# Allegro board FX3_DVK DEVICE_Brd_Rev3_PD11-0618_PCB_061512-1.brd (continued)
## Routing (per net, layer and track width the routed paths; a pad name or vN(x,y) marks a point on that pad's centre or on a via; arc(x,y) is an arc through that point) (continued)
VIO2: length 1.2
  TOP w0.254: U1.F1 64.64,66.55 64.64,67.64 v2(64.71,67.71)
  vias: v2(64.73,68.26)
VIO3: length 1.6
  TOP w0.254: U1.E3 65.23,65.16 65.23,65.16 v2(65.04,65.35)
  BOTTOM w0.381: C111.1 65.27,65.57 v2(65.04,65.35) 65.29,65.1 C110.1
VIO4: length 11
  TOP w0.254: v2(68.24,66.95) 68.03,66.73 68.03,66.73 U1.B1
  TOP w0.381: v1(61.73,92.78) 61.63,92.88 U7.1
  TOP w0.508: R248.1 58.6,109.53 v3(58.17,109.09) ; R250.1 v1(61.54,97.21)
  TOP w0.635: U26.8 v3(58.17,109.09)
  BOTTOM w0.483: C36.1 v1(61.73,92.78)
  BOTTOM w0.508: R249.1 v3(57.21,97.03) ; R248.1 58.6,109.53 v3(58.17,109.09) ; R252.1 v1(62.93,110.93) ; R246.1 v3(58.6,96.96) ; R36.2 v3(65.64,90.11)
VIO5: length 8.7
  TOP w0.254: U1.C11 67.04,58.55 v2(67.04,57.98)
  TOP w0.508: R51.2 v3(22.52,28.65) ; R53.2 v3(22.52,17.09) ; R55.2 v3(22.52,12.01) ; R52.2 v3(22.52,18.87) ; R54.2 v3(22.52,14.55)
  BOTTOM w0.508: R263.1 v3(34.16,113.47)
  BOTTOM w0.635: C197.1 v3(29.08,117.86) ; R262.1 v3(31.62,113.54) ; R176.2 v3(46.68,101.22) ; C212.1 v3(27.94,117.86) ; R186.2 v3(52.38,101.22) ; R110.1 v3(36.83,113.47)
XTALIN: length 19.6
  TOP w0.203: v2(67.44,62.15) 67.2,62.4 U1.C6
  TOP w0.483: Y3.1 77.47,74.08 ; C216.2 v1(77.44,71.93)
  TOP w0.508: 77.47,74.08 C216.2
  SIG2#6 w0.127: v1(77.44,71.93) arc(77.34,71.45) 77.07,71.04 68.71,62.69 arc(68.57,62.59) 68.39,62.55 67.85,62.55 arc(67.56,62.43) v2(67.44,62.15)
XTALOUT: length 20.7
  TOP w0.203: U1.C7 67.24,61.55 v2(67.44,61.35)
  TOP w0.483: v1(80.1,69.51) 80.14,69.48 C217.1 81.64,69.49 81.64,71.94
  TOP w0.508: 81.64,71.94 Y3.3
  SIG2#6 w0.127: v1(80.1,69.51) 77.05,69.51 arc(76.47,69.4) 75.99,69.07 68.89,61.98 arc(68.64,61.81) 68.34,61.75 67.85,61.75 arc(67.56,61.63) v2(67.44,61.35)
N13394127: length 41.3
  TOP w0.254: U1.E10 v2(65.84,58.95)
  SIG2#6 w1.27: 66.65,56.66 66.65,56.14 66.73,56.14 68.29,54.58 68.29,52.03 55.04,38.78 51.45,38.78 43.14,30.48 J74.1
  BOTTOM w0.381: C53.1 65.67,59.12 v2(65.84,58.95)
N13841009: length 2.1
  TOP w0.432: v1(65.53,89.03) 65.58,88.98 U7.8
  BOTTOM w0.483: v1(65.53,89.03) 65.72,89.21 R36.1
N13880067: length 10.3
  TOP w0.432: U6.16 73.86,93.65 75.65,95.44 75.65,96.86 76.96,98.17 R29.2
N13882405: length 10.1
  TOP w0.432: R25.2 80.26,97.16 79.88,97.54 77.83,97.54 76.53,96.23 76.53,95.32 74.21,93 U6.17
N13882880: length 1.8
  TOP w0.432: U6.9 80.71,96.26 R27.2
N13883880: length 1.9
  TOP w0.432: R33.2 80.31,95.12 79.83,95.61 U6.8
N13897864: length 2.1
  TOP w0.432: R32.1 71.83,95.63 72.45,96.26 U6.12
N13897866: length 2.1
  TOP w0.432: U6.15 72.68,94.31 71.97,93.6 R28.1
N13897868: length 2
  TOP w0.432: U6.10 78.11,96.91 v1(77.98,96.78)
  BOTTOM w0.483: R26.1 77.44,96.77 77.45,96.78 v1(77.98,96.78)
N13897870: length 2.2
  TOP w0.432: U6.13 72.7,95.61 71.71,94.61 R24.1
N13929197: length 1.9
  TOP w0.432: U6.2 79.98,91.7 80.32,91.37 C33.1
N13930227: length 2.1
  TOP w0.432: C33.2 80.48,92.27 79.77,92.99 79.14,92.99 U6.4
N13931322: length 1.9
  TOP w0.432: C35.1 80.44,93.28 80.06,93.65 U6.5
N13931334: length 1.8
  TOP w0.432: U6.6 80.31,94.31 80.44,94.18 80.9,94.18 C35.2
N13944533: length 2.2
  TOP w0.432: U6.3 78.33,92.35 78.23,92.46 78.18,92.46 v3(78.13,92.51)
  BOTTOM w0.483: v3(78.13,92.51) 78.18,92.46 78.23,92.46 78.43,92.26 C32.1
N13945074: length 2
  TOP w0.432: U6.7 78.26,94.96 v3(78.13,94.83)
  BOTTOM w0.483: v3(78.13,94.83) 78.16,94.8 C34.1
N16663499: length 1.8
  TOP w0.254: X2.7 v1(75.31,56.88)
  BOTTOM w0.483: v1(75.31,56.88) 75.29,56.9 R43.2
N17020961:
  vias: v3(91.25,29.35) v3(91.25,28.49) v3(92.29,29.66) v3(93.18,29.62)
N17052408: length 3.2
  TOP w0.305: C43.1 71.43,63.2 68.99,63.2 arc(68.8,63.24) U1.A5
N17056303: length 3.2
  TOP w0.305: C46.1 71.43,62.7 68.99,62.7 arc(68.8,62.66) U1.A6
N17073855: length 4.1
  TOP w0.127: v4(95.5,53.1) 95.63,53.1 J48.11 ; v4(95.5,63.64) 95.63,63.64 J48.15 ; v4(95.5,56.02) 95.63,56.02 J48.12 ; J48.16 95.63,66.18 v4(95.5,66.18) ; J48.14 95.63,61.1 v4(95.5,61.1) ; J48.13 95.63,58.31 v4(95.5,58.31)
  vias: v4(92.46,67.07) v4(92.46,52.34) v4(93.47,67.07) v4(93.47,52.34) v4(94.49,66.18) v4(94.49,63.64) v4(94.49,61.1) v4(94.49,58.31) v4(94.49,56.02) v4(94.49,53.1) v4(94.8,48.76) v4(95.4,47.45) v4(95.46,46.45)
N17441604: length 1.8
  TOP w0.254: v2(68.24,65.35) 67.84,64.95 U1.B3
  BOTTOM w0.381: v2(68.24,65.35) 68.98,66.08 69.15,66.08 R47.1
N17441606: length 5
  TOP w0.254: U1.C8 v2(67.44,60.55)
  BOTTOM w0.305: v2(67.44,60.55) 68.24,60.55 68.54,60.25 69.42,60.25 69.44,60.23 69.45,60.23 69.46,60.22 69.6,60.07 69.6,60.07 69.61,60.06 69.61,60.05 69.81,59.86 70.79,59.86 71.13,59.52 R48.1
N17676874: length 1.6
  TOP w0.254: X2.1 v1(79.35,54.38)
  BOTTOM w0.508: R40.2 80.09,54.38 v1(79.35,54.38)
N20153874:
  vias: v3(88.98,55) v3(89.66,55) v3(90.72,54.44) v3(90.69,53.74) v3(92.1,55.2) v3(92.8,55.2)
N20184217: length 15.8
  TOP w0.127: U1.F10 64.45,59.16 64.45,59.16 v2(64.24,58.95)
  SIG2#6 w0.127: v2(64.24,58.95) 63.84,58.55 63.84,57.89 63.47,57.51 63.2,57.51 60.64,54.95 53.84,54.95 v1(53.56,55.23)
  BOTTOM w0.483: R5.1 52.14,56.11 53.02,55.23 v1(53.56,55.23)
N20186132: length 16.7
  TOP w0.127: U1.F9 64.43,59.94 64.43,59.94 v2(64.24,59.75)
  SIG2#6 w0.127: v2(64.24,59.75) 64.24,59.75 63.85,59.35 63.29,59.35 63.05,59.11 63.05,57.9 60.58,55.43 53.99,55.43 53.74,55.68 53.29,56.13 v1(53.08,56.13)
  BOTTOM w0.483: R205.1 52.29,57.78 52.62,57.46 52.62,57.46 52.83,57.25 52.83,56.38 v1(53.08,56.13)
N20187007: length 12.2
  TOP w0.127: U1.F7 64.47,61.58 64.47,61.58 v2(64.24,61.35)
  TOP w0.483: v1(56.32,60.26) 55.76,60.26 R206.1
  SIG1#3 w0.127: v1(56.32,60.26) 56.37,60.26 58.39,58.24 60.9,58.24 61.45,58.8 61.45,59.11 61.68,59.34 63.59,59.34 63.85,59.6 63.85,60.38 63.85,60.95 v2(64.24,61.35)
N20187884: length 10.4
  TOP w0.127: U1.G10 63.63,59.14 63.63,59.14 v2(63.44,58.95)
  SIG1#3 w0.127: v2(63.44,58.95) 63.06,58.56 63.06,57.9 61.83,56.67 v1(55.7,56.67)
  BOTTOM w0.483: R207.1 v1(55.7,56.67)
N20188787: length 15.5
  TOP w0.127: U1.G9 63.84,60.15 v2(63.44,59.75)
  TOP w0.483: R208.1 52.14,57.93 53.48,56.59 v1(53.72,56.59)
  SIG2#6 w0.127: v1(53.72,56.59) 54.77,56.59 55.16,56.19 60.44,56.19 62.01,57.76 62.24,57.99 62.24,58.13 62.24,58.14 62.24,59.11 62.48,59.35 62.81,59.35 63.2,59.75 v2(63.44,59.75)
N20188789: length 15.9
  TOP w0.127: v2(64.24,60.55) 64.46,60.76 64.46,60.76 U1.F8
  SIG2#6 w0.127: v2(64.24,60.55) 64.24,60.55 63.84,60.95 63.84,61.51 63.61,61.74 63.28,61.74 62.49,61.74 62.25,61.98 62.25,62.39 61.38,63.25 60.57,63.25 60.04,63.79 59.94,63.79 59.94,63.79 59.49,63.79 58.56,64.72 55.2,64.72 54.2,65.72 53.39,65.72 53.38,65.73 v1(53.24,65.73)
  BOTTOM w0.483: v1(53.24,65.73) 53.14,65.83 53.14,65.83 52.14,66.84 R209.1
N20188799: length 8.9
  TOP w0.127: v2(62.64,58.95) 62.85,59.16 62.85,59.16 U1.H10
  SIG1#3 w0.127: v2(62.64,58.95) 62.24,58.54 62.24,57.91 61.81,57.48 57.33,57.48 56.52,58.29 56.51,58.29 v1(56.45,58.35)
  BOTTOM w0.483: R210.1 56.29,58.42 56.32,58.39 56.37,58.39 56.41,58.35 v1(56.45,58.35)
N20188809: length 12.3
  TOP w0.127: U1.H9 62.84,59.95 62.84,59.95 v2(62.64,59.75)
  TOP w0.483: v1(52.81,61.62) 52.81,61.66 52.14,62.33 R211.1
  SIG2#6 w0.127: v1(52.81,61.62) 52.95,61.76 56.56,61.76 58.15,60.17 60.61,60.17 60.63,60.15 62.26,60.15 62.64,59.77 v2(62.64,59.75)
N20189728: length 8
  TOP w0.127: U1.J10 62.06,59.17 62.06,59.17 v2(61.84,58.95)
  SIG1#3 w0.127: v1(56.31,59.32) 56.32,59.32 56.39,59.25 56.55,59.25 57.93,57.87 58.31,57.87 58.31,57.86 61,57.86 61.84,58.71 v2(61.84,58.95)
  BOTTOM w0.483: R212.1 56.21,59.44 56.32,59.32 v1(56.31,59.32)
N20189730: length 13.3
  TOP w0.127: v2(61.84,59.75) 62.06,59.97 62.06,59.97 U1.J9
  SIG2#6 w0.127: v1(53.53,57.38) 53.53,57.37 53.78,57.11 59.97,57.11 61.45,58.6 61.45,59.35 v2(61.84,59.75)
  BOTTOM w0.483: R213.1 52.14,58.96 52.83,58.26 52.83,58.13 53.46,57.5 53.46,57.46 v1(53.53,57.38)
N20189740: length 8.6
  TOP w0.254: 61.21,58.29 61.44,58.52 U1.K11
  TOP w0.483: R214.1 56.38,62.1 57.02,61.46 57.02,59.96 58.98,58 60.92,58 61.21,58.29
N20189750: length 8.1
  TOP w0.203: U1.L10 60.64,59.35 60.63,59.34 59.87,59.34 59.82,59.29
  TOP w0.483: R215.1 56,63.58 56.69,63.58 56.73,63.54 56.76,63.54 57.76,62.53 57.76,60.39 58.87,59.29 59.82,59.29
N20190677: length 11.4
  TOP w0.127: U1.K10 61.23,59.14 61.23,59.14 v2(61.04,58.95)
  TOP w0.483: v1(52.95,59.11) 52.95,59.11 52.14,59.92 R216.1
  SIG2#6 w0.127: v1(52.95,59.11) 53.99,59.11 55.22,57.88 59.96,57.88 60.59,58.51 60.59,58.51 61.03,58.95 v2(61.04,58.95)
N20190679: length 11.1
  TOP w0.127: v2(61.04,59.75) 61.24,59.94 61.24,59.94 U1.K9
  SIG2#6 w0.127: v1(52.96,60.38) 53.44,60.85 53.71,60.85 53.71,60.85 54.08,60.85 54.08,60.85 56.1,60.85 56.18,60.77 56.57,60.77 57.12,60.23 57.12,60.22 57.99,59.35 60.65,59.35 61.04,59.75 v2(61.04,59.75)
  BOTTOM w0.483: v1(52.96,60.38) 52.86,60.49 52.85,60.49 52.14,61.19 R217.1
N20190689: length 8.1
  TOP w0.127: U1.J8 62.05,60.76 v2(61.84,60.55)
  SIG1#3 w0.127: v1(56.45,62.98) 56.98,62.98 59.79,60.17 60.62,60.17 60.64,60.14 61.24,60.14 61.65,60.55 v2(61.84,60.55)
  BOTTOM w0.483: v1(56.45,62.98) 56.44,62.97 56.05,62.97 56.03,62.99 R218.1
N20190699: length 9.8
  TOP w0.127: U1.G8 v2(63.44,60.55)
  SIG1#3 w0.127: v2(63.44,60.55) 63.04,60.15 61.69,60.15 61.45,59.91 61.45,59.59 61.22,59.35 58.22,59.35 v1(56.37,61.21)
  BOTTOM w0.483: v1(56.37,61.21) R219.1
N20191634: length 9.1
  TOP w0.127: U1.J6 62.03,62.34 62.03,62.34 v2(61.84,62.15)
  SIG1#3 w0.127: v2(61.84,62.15) 61.84,62.15 61.43,61.74 60.85,61.74 60.4,62.19 60.4,62.32 60.17,62.55 59.62,62.55 56.92,65.25 56.92,65.61 56.47,66.06 56.47,66.07 v1(56.44,66.09)
  BOTTOM w0.483: R220.1 v1(56.44,66.09)
N20191636: length 7.7
  TOP w0.127: U1.K8 61.29,60.79 61.29,60.79 v2(61.04,60.55)
  SIG1#3 w0.127: v1(56.35,64.28) 56.35,64.15 59.96,60.55 v2(61.04,60.55)
  BOTTOM w0.381: R221.1 55.81,64.77 56.3,64.28 v1(56.35,64.28)
N20191646: length 10.6
  TOP w0.127: v2(61.04,61.35) 61.25,61.56 U1.K7
  TOP w0.483: v1(52.87,63.47) 52.83,63.51 52.82,63.51 52.2,64.14 R222.1
  SIG2#6 w0.127: v2(61.04,61.35) 60.65,61.35 60.26,61.75 57.65,61.75 56.88,62.52 56.07,62.52 55.55,63.04 53.3,63.04 v1(52.87,63.47)
N20191656: length 12
  TOP w0.127: v2(61.84,61.35) 62.05,61.55 62.05,61.56 U1.J7
  SIG2#6 w0.127: v1(53.42,63.8) 53.55,63.93 54.44,63.93 54.91,63.45 58.6,63.45 59.45,62.6 60.13,62.6 60.65,62.08 60.65,61.96 60.86,61.75 61.41,61.75 61.81,61.35 v2(61.84,61.35)
  BOTTOM w0.483: R223.1 52.2,65.02 53.42,63.81 v1(53.42,63.8)
N20192599: length 13.1
  TOP w0.127: U1.H7 62.87,61.57 v2(62.64,61.35)
  TOP w0.483: R224.1 v1(56.49,69.22)
  SIG1#3 w0.127: v1(56.49,69.22) 57.16,68.54 57.16,67.31 60.33,64.14 61.21,64.14 62.01,63.34 62.81,63.34 63.04,63.1 U1.H7 v2(62.64,61.35)
N20192601: length 10.5
  TOP w0.127: U1.G7 63.65,61.56 63.65,61.55 v2(63.44,61.35)
  TOP w0.483: v1(56.46,65.17) 56.18,65.17 55.7,65.66 R225.1
  SIG1#3 w0.127: v1(56.46,65.17) 56.46,65.15 56.81,64.8 59.85,61.76 60.18,61.76 60.65,61.3 60.65,61.19 60.88,60.95 62.48,60.95 63.05,60.95 63.44,61.35 v2(63.44,61.35)
N20192611: length 15.2
  TOP w0.127: v2(63.44,62.95) 63.65,62.74 U1.G6
  TOP w0.483: R226.1 52.3,69.6 v1(52.79,69.1)
  SIG2#6 w0.127: v2(63.44,62.95) 63.44,62.95 63.04,63.35 63.04,63.94 62.83,64.15 62.49,64.15 62.24,64.4 62.24,64.71 62,64.95 60.17,64.95 60.17,64.95 60.08,64.95 59.85,65.19 59.83,65.19 56.91,68.1 55.17,68.1 54.62,68.65 53.25,68.65 52.8,69.1 v1(52.79,69.1)
N20192621: length 11.2
  TOP w0.127: U1.K6 61.04,62.15 v2(61.04,62.15)
  TOP w0.483: R227.1 52.14,65.94 52.68,65.4 52.68,65.4 53.31,64.77 v1(53.33,64.77)
  SIG2#6 w0.127: v1(53.33,64.77) 53.39,64.83 54.07,64.83 55.07,63.84 58.85,63.84 59.71,62.98 60.21,62.98 v2(61.04,62.15)
N20193572: length 12.3
  TOP w0.127: U1.H8 62.86,60.77 62.86,60.77 v2(62.64,60.55)
  SIG2#6 w0.127: v2(62.64,60.55) 62.64,60.65 62.35,60.95 58.88,60.95 58.62,61.21 57.65,61.21 56.72,62.14 53.28,62.14 v1(53.21,62.2)
  BOTTOM w0.483: R228.1 52.14,63.23 53.16,62.2 v1(53.21,62.2)
N20193574: length 21.1
  TOP w0.127: U1.G5 63.66,63.53 v2(63.44,63.75)
  SIG1#3 w0.127: v1(53.35,53.93) 53.99,53.93 56.34,56.29 62.25,56.29 63.61,57.66 63.61,57.66 63.84,57.89 63.84,59.11 64.08,59.34 64.41,59.34 64.65,59.59 64.65,62.48 63.44,63.68 v2(63.44,63.75)
  BOTTOM w0.483: v1(53.35,53.93) 53.34,53.93 52.53,54.74 R229.1
N20193584: length 10.1
  TOP w0.127: v2(62.64,62.15) 62.64,62.15 U1.H6
  TOP w0.483: v1(56.42,66.88) 56.29,66.88 55.73,67.44 R230.1
  SIG1#3 w0.127: v1(56.42,66.88) 56.49,66.81 56.49,66.81 57.57,65.74 57.57,65.13 59.77,62.93 60.19,62.93 60.58,62.54 62.25,62.54 v2(62.64,62.15)
N20193594: length 11.2
  TOP w0.127: v2(61.04,63.75) U1.K5
  TOP w0.483: v1(53.17,66.71) 53.1,66.78 53.1,66.82 52.14,67.77 R231.1
  SIG2#6 w0.127: v2(61.04,63.75) 60.64,63.75 60.18,64.2 59.74,64.2 59.52,64.42 59.51,64.42 58.29,65.65 55.51,65.65 54.44,66.72 53.18,66.72 v1(53.17,66.71)
N20194553: length 10.7
  TOP w0.127: v2(62.64,62.95) 62.43,63.16 U1.J5
  SIG1#3 w0.127: v2(62.64,62.95) 62.64,62.94 60.99,62.94 56.47,67.46 v1(56.47,68.59)
  BOTTOM w0.483: R232.1 56.27,68.33 56.47,68.53 v1(56.47,68.59)
N20195482: length 13.1
  TOP w0.127: U1.H5 v2(62.64,63.75)
  SIG2#6 w0.127: v2(62.64,63.75) 62.45,63.75 62.06,64.14 60.78,64.14 60.34,64.58 59.9,64.58 59.68,64.8 59.67,64.8 56.87,67.61 53.54,67.61 52.96,68.19 v1(52.96,68.19)
  BOTTOM w0.483: R233.1 52.2,68.71 52.72,68.19 v1(52.96,68.19)
N20198119: length 19
  TOP w0.127: U1.G4 63.67,64.32 63.67,64.32 v2(63.44,64.55)
  TOP w0.483: v1(53.44,74.93) 52.14,74.93 R234.1
  SIG2#6 w0.127: v2(63.44,64.55) 63.45,64.55 63.85,64.95 63.85,65.76 63.85,65.76 63.85,68.12 57.67,74.29 55.53,74.29 54.65,75.17 53.68,75.17 v1(53.44,74.93)
N20199051: length 16.9
  TOP w0.127: U1.H4 v2(62.64,64.55)
  TOP w0.483: R235.1 52.87,73.15 v1(52.9,73.13)
  SIG2#6 w0.127: v2(62.64,64.55) 63.04,64.94 63.04,66.31 62.81,66.54 62.49,66.54 62.25,66.79 62.25,67.67 58.48,71.43 56.11,71.43 55.11,72.43 55.09,72.43 54.22,73.3 53.08,73.3 v1(52.9,73.13)
N20199985: length 9.8
  TOP w0.254: U1.L4 60.21,64.15
  TOP w0.483: R236.1 55.73,70.96 56.83,70.96 57.57,70.22 57.57,66.71 60.13,64.15 60.21,64.15
N21712030: length 4
  TOP w0.508: Q13.3 45.89,49.52 R301.1
N21712032: length 2
  TOP w0.508: R300.2 40.96,47.51 Q13.1
N21712149: length 1.9
  TOP w0.508: D14.2 46.81,47.64 R301.2
N21712617: length 1.6
  TOP w0.508: R302.1 31.69,3.31 v1(32.41,3.31)
  BOTTOM w0.508: Q14.3 v1(32.41,3.31)
N21712619: length 2.9
  TOP w0.508: R306.2 v1(32,7.03)
  BOTTOM w0.508: v1(32,7.03) 32,6.65 Q14.1
N21712675: length 2.6
  TOP w0.508: D18.2 34.14,2.34 R302.2
N21838652: length 5.3
  TOP w0.127: U1.D1 66.24,66.55 v2(66.64,66.95)
  TOP w0.483: R254.1 v1(67.11,70.85)
  SIG1#3 w0.127: v1(67.11,70.85) 66.64,70.38 v2(66.64,66.95)
N21838662: length 6.6
  TOP w0.127: U1.D2 66.24,65.75 v2(66.64,66.15)
  TOP w0.483: R255.1 v1(68.13,70.85)
  SIG1#3 w0.127: v1(68.13,70.85) 68.1,70.85 67.05,69.8 67.05,66.55 v2(66.64,66.15)
N21838672: length 7
  TOP w0.127: U1.D3 66.24,64.95 v2(65.84,65.35)
  TOP w0.483: R256.1 v1(65.08,70.82)
  SIG1#3 w0.127: v1(65.08,70.82) 65.39,70.5 65.39,65.8 v2(65.84,65.35)
N21838834: length 9.9
  TOP w0.127: U1.C4 67.2,64.31 67.2,64.31 v2(67.44,64.55)
  TOP w0.483: R261.1 v1(72.19,70.82)
  SIG1#3 w0.127: v1(72.19,70.82) 72.16,70.78 72.16,69.66 70.13,67.63 70.13,66.61 68.46,64.94 67.79,64.94 67.44,64.6 v2(67.44,64.55)
N21839162: length 7.8
  TOP w0.127: U1.D4 66.44,64.35 66.44,64.35 v2(66.64,64.55)
  TOP w0.483: R257.1 v1(66.1,70.85)
  SIG1#3 w0.127: v2(66.64,64.55) 66.25,64.94 66.25,70.7 v1(66.1,70.85)
N21839172: length 5.8
  TOP w0.127: v2(67.44,66.95) 67.04,66.55 U1.C1
  TOP w0.483: R258.1 v1(69.15,70.85)
  SIG1#3 w0.127: v1(69.15,70.85) 67.44,69.15 v2(67.44,66.95)
N21839182: length 7.1
  TOP w0.127: U1.C2 67.04,65.75 v2(67.44,66.15)
  TOP w0.483: R259.1 v1(70.16,70.82)
  SIG1#3 w0.127: v2(67.44,66.15) 67.44,66.16 67.84,66.55 67.84,68.49 v1(70.16,70.82)
N21839192: length 10.9
  TOP w0.127: U1.D5 66.43,63.54 66.43,63.54 v2(66.64,63.75)
  TOP w0.483: R260.1 v1(71.18,70.82)
  SIG1#3 w0.127: v1(71.18,70.82) 71.18,69.34 69.6,67.76 69.6,66.95 68.39,65.74 67.28,65.74 67.05,65.51 67.05,65.19 67.05,65.18 67.05,64.71 67.05,64.71 67.05,64.15 v2(66.64,63.75)
N21886398: length 3.9
  TOP w0.483: U45.5 21.31,100.2 20.39,101.12 R11.1
N21902204: length 9.6
  TOP w0.127: v2(61.04,66.15) 61.24,65.95 U1.K2
  SIG1#3 w0.127: v2(61.04,66.15) 61.04,66.15 60.64,66.55 60.64,67.65 60.05,68.24 59.5,68.24 59.17,68.56 59.17,68.64 56.55,71.26 v1(56.55,72.05)
  BOTTOM w0.483: R6.1 56.38,71.88 v1(56.55,72.05)
N21902237: length 9.9
  TOP w0.127: U1.J4 62.07,64.33 v2(61.84,64.55)
  SIG1#3 w0.127: v2(61.84,64.55) 61.84,64.55 61.44,64.95 60.08,64.95 59.85,65.19 58.39,66.64 57.8,67.24 57.8,68.82 56.56,70.05 56.54,70.05 v1(56.49,70.1)
  BOTTOM w0.483: R12.1 v1(56.49,70.1)
N21902264: length 9.2
  TOP w0.127: v2(61.04,66.95) 61.26,66.74 U1.K1
  TOP w0.483: v1(56.87,72.68) 56.77,72.77 R13.1
  SIG1#3 w0.127: v2(61.04,66.95) 61.04,68.5 v1(56.87,72.68)
N21902291: length 12.4
  TOP w0.127: U1.J2 62.06,65.94 v2(61.84,66.15)
  SIG1#3 w0.127: v1(56.4,74.85) 61.45,69.8 61.45,66.54 v2(61.84,66.15)
  BOTTOM w0.483: v1(56.4,74.85) 56.39,74.85 56.09,74.55 R14.1
N21902318: length 12.9
  TOP w0.127: U1.J3 v2(61.84,65.35)
  SIG2#6 w0.127: v1(52.96,69.99) 53.09,69.99 53.28,69.8 56.16,69.8 56.3,69.66 56.79,69.66 58.49,67.96 58.5,67.96 58.79,67.67 58.79,66.76 59.81,65.74 60.41,65.74 60.41,65.74 60.88,65.74 60.88,65.74 61.21,65.74 61.6,65.35 v2(61.84,65.35)
  BOTTOM w0.483: v1(52.96,69.99) 52.64,69.99 R15.1
N21902345: length 12.8
  TOP w0.127: U1.J1 62.06,66.74 v2(61.84,66.95)
  SIG1#3 w0.127: v1(56.57,75.97) 61.84,70.7 v2(61.84,66.95)
  BOTTOM w0.483: R16.1 56.14,75.56 56.55,75.97 v1(56.57,75.97)
N21902372: length 14.3
  TOP w0.127: v2(62.64,66.15) 62.86,65.93 62.86,65.93 U1.H2
  SIG2#6 w0.127: v2(62.64,66.15) 62.4,66.15 61.99,66.55 61.68,66.55 61.44,66.8 61.44,67.11 61.43,67.12 61.43,67.95 58.34,71.04 55.07,71.04 54.34,71.76 52.92,71.76 v1(52.92,71.77)
  BOTTOM w0.483: v1(52.92,71.77) 52.63,71.77 R17.1
N21902399: length 14.8
  TOP w0.127: v2(62.64,65.35) 62.87,65.13 62.87,65.12 U1.H3
  TOP w0.483: R18.1 52.64,70.88 v1(52.94,70.88)
  SIG2#6 w0.127: v2(62.64,65.35) 62.64,65.37 62.26,65.75 61.68,65.75 61.45,65.99 61.45,66.3 61.19,66.55 60.88,66.55 60.64,66.8 60.64,67.62 60.14,68.12 59.61,68.12 59.22,68.51 59.22,69.52 58.09,70.65 54.04,70.65 53.81,70.88 v1(52.94,70.88)
N21902426: length 18.5
  TOP w0.127: v2(64.24,64.55) 64.44,64.35 U1.F4
  SIG1#3 w0.127: v2(64.24,64.55) 64.15,64.55 63.85,64.85 63.85,66.31 63.85,66.31 63.85,67.41 63.48,67.77 63.48,71.48 57.03,77.93 v1(57.03,77.94)
  BOTTOM w0.483: v1(57.03,77.94) 57.02,77.94 56.68,77.6 R20.1
N21902453: length 16.4
  TOP w0.127: U1.G2 v2(63.44,66.15)
  SIG2#6 w0.127: v2(63.44,66.15) 63.44,66.39 63.05,66.79 63.05,68.31 62.51,68.84 62.51,68.84 60.79,70.56 57.49,73.86 54.75,73.86 54.34,74.27 52.77,74.27 v1(52.7,74.21)
  BOTTOM w0.483: R21.1 52.54,74.04 v1(52.7,74.21)
N21902480: length 15.8
  TOP w0.127: U1.G3 63.67,65.12 v2(63.44,65.35)
  SIG1#3 w0.127: v2(63.44,65.35) 63.44,65.35 63.05,65.73 63.05,70.2 v1(56.36,76.89)
  BOTTOM w0.483: v1(56.36,76.89) 56.35,76.89 56.04,76.58 R44.1
N21902507: length 19.2
  TOP w0.127: U1.F3 64.44,65.16 v2(64.24,65.35)
  SIG1#3 w0.127: v2(64.24,65.35) 64.26,65.35 64.67,65.76 64.67,67.1 64.12,67.64 64.12,71.6 56.41,79.31 v1(56.33,79.31)
  BOTTOM w0.483: R45.1 55.7,78.79 56.22,79.31 v1(56.33,79.31)
N21902708: length 16.5
  TOP w0.127: U1.F5 v2(64.24,63.75)
  SIG1#3 w0.127: v1(56.42,73.39) 56.42,73.39 56.1,73.07 56.1,71.17 58.79,68.48 58.79,67.01 60.04,65.75 62.03,65.75 62.25,65.53 62.25,64.38 62.49,64.14 63.87,64.14 64.24,63.76 v2(64.24,63.75)
  BOTTOM w0.483: v1(56.42,73.39) 56.42,73.39 56.28,73.53 R49.1
N21902721: length 22.2
  TOP w0.127: U1.E1 65.44,66.55 v2(65.84,66.95)
  SIG2#6 w0.127: v2(65.84,66.95) 65.84,68.76 62.93,71.67 62.93,74.03 58.1,78.86 53.74,78.86 52.74,77.86 v1(52.74,77.86)
  BOTTOM w0.483: R50.1 52.47,77.6 v1(52.74,77.86)
N21902734: length 27.2
  TOP w0.127: v2(65.84,63.75) 65.61,63.52 U1.E5
  SIG2#6 w0.127: v2(65.84,63.75) 66.24,64.14 66.24,66.73 66.25,66.74 66.25,67.11 66.28,67.14 66.28,68.91 66.24,68.95 64.64,70.55 64.64,70.56 64.23,70.97 64.23,74.6 58.95,79.87 53.73,79.87 52.87,79.01 52.87,79.01 v1(52.84,78.98)
  BOTTOM w0.483: v1(52.84,78.98) 52.51,78.98 R56.1
N21902747: length 23.1
  TOP w0.127: v2(65.84,64.55) 65.64,64.34 U1.E4
  SIG2#6 w0.127: v1(53.09,77.33) 53.09,77.34 58.46,77.34 62.5,73.3 62.5,71.49 65.44,68.55 65.44,65.09 65.84,64.68 v2(65.84,64.55)
  BOTTOM w0.483: R57.1 52.38,76.58 53.09,77.29 v1(53.09,77.33)
N21904014: length 1.3
  TOP w0.254: v1(58.74,4.64) 58.8,4.7 U17.3
  BOTTOM w0.381: R237.1 58.62,4.77 v1(58.74,4.64)
N21904020: length 3.2
  TOP w0.279: R239.1 59,9.77 58.8,9.57 U17.8
  TOP w0.381: R238.2 R239.1
N21904073: length 3.4
  TOP w0.279: U17.7 59.3,9.05 59.83,9.59 60.76,9.59 61.04,9.87 C129.1
N21905805: length 3.5
  TOP w0.508: R141.1 R144.2 37.03,44.71 37.47,44.27 U19.7
N21905847: length 2.2
  TOP w0.508: R139.1 36.19,43.11 U19.8
N21905950: length 3.2
  TOP w0.483: R240.2 R242.2 27.05,12.33 27.3,12.08 U20.7
N21905997: length 2.1
  TOP w0.483: R241.1 26.04,12.76 U20.8
N21906513: length 3.2
  TOP w0.483: U23.7 38.1,11.86 37.72,12.25 R245.2 R243.2
N21906562: length 2.1
  TOP w0.483: U23.8 36.83,11.94 36.7,12.07 R244.1
N21921971: length 9.3
  TOP w0.483: SW40.6 35.36,106.74 36.78,108.17 U44.3
  BOTTOM w0.381: U44.3 36.83,109.52 R110.2
N21921973: length 8.7
  TOP w0.483: SW40.7 34.09,109.32 U44.2
  BOTTOM w0.381: U44.2 34.16,109.55 R263.2
N21921975: length 9.1
  TOP w0.483: U44.1 31.7,107.95 32.82,106.83 SW40.8
  BOTTOM w0.381: R262.2 31.62,109.55 U44.1
N21922075: length 2.5
  BOTTOM w0.381: U44.7 34.23,117.09 R111.1
N22050803: length 1.7
  TOP w0.508: R307.1 v1(52.9,4.9)
  BOTTOM w0.508: v1(52.9,4.9) 52.9,3.98 Q15.3
N22050805: length 2.8
  TOP w0.508: v1(54.48,3.94) 54.43,3.99 R308.2
  BOTTOM w0.508: Q15.1 53.91,3.36 v1(54.48,3.94)
N22050813: length 2
  TOP w0.508: R307.2 52,2.39 D15.2
N22050947: length 1.7
  TOP w0.508: R309.1 v1(75.89,1.59)
  BOTTOM w0.508: Q16.3 75.89,2.22 v1(75.89,1.59)
N22050949: length 2.2
  TOP w0.508: v1(79.05,3.36) 78.61,2.92 R310.2
  BOTTOM w0.508: Q16.1 v1(79.05,3.36)
N22050957: length 4.6
  TOP w0.508: D16.2 73.57,1.56 74.42,2.41 R309.2
N22051184: length 1.9
  TOP w0.508: R311.1 46.79,5.53 v1(46.74,5.59)
  BOTTOM w0.508: v1(46.74,5.59) 46.49,5.83 Q17.3
N22051186: length 1.8
  BOTTOM w0.508: R312.2 46.92,2.04 Q17.1
N22051194: length 1.8
  TOP w0.508: R311.2 47.44,4.32 D17.2

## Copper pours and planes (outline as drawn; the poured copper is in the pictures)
5V_DC_INPUT on TOP: 79.12,18.83 79.88,19.59 86.79,19.59 87.12,19.25 87.12,8 86.36,7.24 83.12,7.24 82.65,6.76 82.65,4.92 81.94,4.21 75.03,4.21 74.42,4.83 74.42,7.58 75.13,8.29 78.66,8.29 79.12,8.75
5V_DC_INPUT on BOTTOM: 75.82,8.89 78.61,8.89 82.04,12.32 82.04,19.56 82.8,20.32 85.85,20.32 87.5,18.67 87.5,7.87 83.95,4.32 75.82,4.32 74.93,5.21 74.93,8
AVDD on TOP: 68.92,61.92 68.86,61.86 68.86,61.46 69.16,61.16 69.16,60.67 69.32,60.51 69.82,60.51 69.92,60.61 69.92,61.52 69.53,61.92
AVDD on BOTTOM: 68.91,61.93 68.91,60.78 69.1,60.59 69.52,60.59 69.92,60.19 71.09,60.19 71.09,61.33 70.89,61.54 69.59,61.54 69.39,61.74 69.39,61.92 69.35,61.96 68.94,61.96
AVDD on BOTTOM: 74.45,66.8 74.56,66.68 76.46,66.68 76.52,66.74 76.52,68.07 76.26,68.33 76.23,68.36 74.65,68.36 74.45,68.16
AVDD on SIG1#3: 70.29,59.25 77.37,59.25 77.74,59.61 77.74,66.79 76.81,67.73 74.81,67.73 68.83,61.74 68.83,61.74 68.79,61.71 68.79,60.74
GND on TOP: 45.94,37.59 42.8,37.59 42.75,37.54 41.94,37.54 41.67,37.27 41.67,34.88 41.9,34.65 45.94,34.65
GND on TOP: 89.53,33.78 88.52,33.78 88.27,34.04 87.76,34.04 87.63,33.91 87.63,32.26 88.01,31.88 89.15,31.88 89.53,32.26
GND on TOP: 68.07,17.3 71.63,17.3 71.63,17.33 73.61,17.33 74.42,18.14 74.42,20.85 74.16,21.12 74.16,24.93 74.12,24.97 74.12,26.11 73.96,26.26 73.3,26.26 73.23,26.2 73.23,25.53 73.1,25.4 68.96,25.4 68.07,24.51
GND on TOP: 83.06,6.6 86.11,6.6 86.61,6.1 86.61,1.4 86.11,0.89 81.79,0.89 81.66,1.02 81.66,3.3 81.92,3.56 82.3,3.56 82.93,4.19 82.93,6.48
GND on TOP: 57.28,4.32 57.28,3.05 57.53,2.79 57.53,0.89 57.28,0.64 55.88,0.64 55.37,1.14 55.37,4.06 55.63,4.32
GND on TOP: 63.88,11.3 63.5,10.92 63.5,7.37 63.75,7.11 66.67,7.11 67.18,7.62 67.18,10.92 66.8,11.3
GND on TOP: 22.68,1.5 27.71,1.5 28.42,2.21 28.42,4.24 27.69,4.98 27.69,6.83 27.33,7.19 25.53,7.19 24.79,7.92 24.79,10.46 24.43,10.82 21.95,10.82 21.31,10.19 21.31,2.87
GND on TOP: 93.08,58.82 91.87,58.82 91.74,58.94 91.74,59.51 91.72,59.54 90.81,59.54 90.64,59.37 90.64,58.61 91.06,58.2 93.07,58.2 93.08,58.21
GND on TOP: 38.97,1.58 38.98,1.59 39.22,1.59 39.32,1.68 39.32,3.96 38.58,4.7 38.58,6.72 38.39,6.91 36.42,6.91 35.69,7.65 35.69,10.19 35.33,10.54 33.15,10.54 32.77,10.16 32.77,4.82 34.4,3.18 36.94,3.18 37.5,2.62 37.5,1.72 37.64,1.58
GND on TOP: 31.93,93.59 32.23,93.29 35.58,93.29 35.79,93.5 35.79,96.36 35.59,96.56 32.46,96.56 31.93,96.03
GND on TOP: 25.25,118.31 15.79,118.31 14.73,117.25 14.73,109.25 15.25,108.73 20.33,108.73 20.92,109.32 20.92,114.67 21.68,115.43 25.12,115.43 25.55,115.87 25.55,118
GND on TOP: 85.93,29.84 84.91,28.83 83.57,28.83 83.31,28.57 83.31,25.27 83.57,25.02 90.03,25.02 90.17,25.16 90.17,29.09 89.42,29.84
GND on TOP: 93.47,49.39 93.47,45.92 92.96,45.42 91.31,45.42 90.68,46.05 90.68,48.72 91.35,49.39
GND on TOP: 38.13,36.78 38.13,34.85 37.84,34.56 35.31,34.56 34.95,34.91 34.95,38.63 35.4,39.08 37.89,39.08 37.89,37.02
GND on TOP: 87.87,20.21 86.52,20.21 85.86,20.87 85.86,22.73 86.35,23.22 93.18,23.22 94.09,22.31 94.09,13.59 93.45,12.94 91.08,12.94 89.77,14.26 89.77,19.6 89.14,20.23 87.89,20.23
GND on BOTTOM: 72.22,92.37 75.14,92.37 75.34,92.57 75.34,94.24 75.33,94.25 72.8,94.25 72.22,93.68
GND on BOTTOM: 21.53,11.41 21.53,2.16 22.93,0.76 28.06,0.76 28.39,1.09 28.39,3.43 25.14,6.68 25.14,11.33 24.88,11.58 21.71,11.58
GND on BOTTOM: 62.65,68.53 62.65,67.86 62.69,67.82 63.26,67.82 63.35,67.72 63.35,67.17 63.24,67.05 63.24,66.79 63.31,66.72 63.72,66.72 63.89,66.88 63.89,68.49 63.84,68.53
GND on BOTTOM: 70.74,63.7 70.86,63.58 74.46,63.58 74.96,64.07 75.68,64.07 77.15,65.55 77.15,66.48 77.09,66.54 76.29,66.54 76.17,66.41 74.77,66.41 74.74,66.38 74.74,65.32 74.22,64.81 70.87,64.81 70.75,64.68 70.75,63.71
GND on BOTTOM: 32.92,11.44 32.92,6.76 32.09,5.94 32.09,4.46 32.92,3.63 32.92,2.19 32.9,2.17 32.9,1.47 33.61,0.75 34.34,0.75 34.32,0.78 34.32,0.8 39.45,0.8 39.78,1.13 39.78,3.46 36.53,6.72 36.53,11.36 36.27,11.62 33.1,11.62
GND on BOTTOM: 80.9,3.94 80.9,1.65 86.61,1.65 86.61,3.94
GND on BOTTOM: 73.21,60.07 71.58,60.07 71.41,60.24 71.41,61.57 71.16,61.82 69.76,61.82 69.65,61.93 69.65,62.35 69.66,62.36 72.58,62.36 73.39,61.55 73.39,60.25
GND on BOTTOM: 87.65,19.64 87.64,19.64 86.15,21.13 86.15,22.33 86.7,22.89 92.79,22.89 93.92,21.76 93.92,14.59 92.97,13.64 90.61,13.64 89.15,15.1 89.15,18.14
GND on BOTTOM: 74.17,0.69 74.17,4.71 71.46,7.42 68.52,7.42 65.09,10.85 61.61,10.85 60.72,9.97 60.72,2.62 62.66,0.69
GND on BOTTOM: 35.9,35.09 36.2,34.8 44.04,34.8 44.56,35.31 44.56,42.69 43.31,43.94 36.83,43.94 35.9,43.01
GND on BOTTOM: 67.88,68.73 67.88,68 67.93,67.94 67.94,67.94 68.56,67.94 68.61,68 69.61,68 69.66,68.05 69.66,68.68 69.61,68.73
GND on BOTTOM: 73.66,24.99 69.24,24.99 67.64,23.39 67.64,20.45 68.55,19.53 73.66,19.53 74.52,20.4 74.52,24.13
GND on BOTTOM: 60.9,57.02 60.9,56.13 61.96,55.07 68.2,55.07 68.64,55.52 68.64,56.9 66.36,56.9 66.23,57.02
GND on BOTTOM: 74.35,98.04 74.35,99.36 74.13,99.58 72.55,99.58 72.49,99.53 72.58,98.04
GND on BOTTOM: 87.81,29.84 87.81,25.65 87.25,25.1 84.86,25.1 84.61,25.35 84.61,29.69 84.84,29.92 87.73,29.92
GND on GND1#2, GND2#7: 0.64,0.64 0.64,120.01 95.88,120.01 95.88,0.64
V1P2 on TOP: 46.49,39.76 47.42,38.83 47.42,35.13 48.39,34.16 52.32,34.16 52.58,34.42 52.58,37.09 55.55,40.07 55.55,44.51 53.96,46.1 42.55,46.1 41.4,44.96 40.51,44.96 40.39,45.09 40.39,47.82 39.88,48.33 34.04,48.33 33.02,47.32 33.02,40.26 33.53,39.75 40.77,39.75 40.78,39.76
V1P2 on BOTTOM: 51.5,33.34 50.58,34.26 50.58,37.63 51.31,38.35 51.31,42.6 51.27,42.64 51.27,43.47 50.55,44.2 31.47,44.2 22.08,53.58 22.08,78.81 34.42,91.15 61.95,91.15 65.47,87.63 70.64,87.63 76.67,81.59 76.67,69.15 76.11,68.6 72.35,68.6 72.33,68.62 72.33,69.05 72.1,69.29 59.85,69.29 59.82,69.32 57.62,69.32 57.62,71.97 56.42,73.17 49.63,73.17 48.41,71.95 48.41,67.42 48.42,67.42 48.42,54.34 49.34,53.42 58.9,53.42 61.12,51.2 61.12,37.81 60.27,36.96 60.27,35.21 58.4,33.34
V1P8 on TOP: 28.09,11.99 28.09,8.44 28.31,8.22 32.34,8.22 32.46,8.34 32.46,13.26 32.46,13.26 32.46,13.86 28.03,18.29 25.78,18.29 25.27,17.78 25.27,13.64 25.49,13.43 27.38,13.43 27.43,13.48 27.43,14.22 27.54,14.33 28.98,14.33 29.08,14.23 29.08,12.95 28.32,12.19 28.3,12.19
V1P8 on BOTTOM: 30.07,8.34 32.15,10.43 32.15,14.02 27.85,18.32 25.47,18.32 24.63,17.48 24.63,14.84 24.66,14.81 24.66,13.65 25.87,12.44 25.87,9.16 26.69,8.34
V1P8 on SIG2#6: 82.45,2.46 92.99,13 92.99,45.48 95.23,47.71 95.23,87.38 92.31,90.3 79.88,90.3 78.39,88.81 78.39,79.92 82.52,75.79 82.52,67.08 86.67,62.93 86.67,52.98 82.14,48.44 82.14,43.78 71.84,33.48 60.55,33.48 59.85,34.19 50.57,34.19 42.87,26.48 32.03,26.48 25.18,19.63 25.18,5.5 28.23,2.46
V2P5 on TOP: 38.96,11.79 38.96,8.71 40.31,7.36 42.86,7.36 43.27,6.95 46.58,6.95 46.91,7.28 46.91,11.25 44.83,13.34 40.45,13.34 39.69,12.57 39.69,12.51
V2P5 on BOTTOM: 37.08,12.7 37.09,12.7 37.76,12.03 37.76,7.7 40.13,5.33 40.13,1.27 40.64,0.76 45.21,0.76 45.59,1.14 45.59,2.03 45.34,2.29 44.07,2.29 43.56,2.79 43.56,5.84 44.99,7.27 47.62,7.27 48.01,7.66 48.01,7.72 53.39,13.11 64.31,13.11 66.25,15.05 66.25,28.78 61.96,33.06 56.44,33.06 55.02,31.65 50.8,31.65 44.16,25.01 30.44,25.01 28.83,23.4 28.83,19.8 29.86,18.77 31.01,18.77
V3P3 on TOP: 72.36,91.18 72.47,91.18 72.72,91.43 73.94,91.43 74.44,90.93 76.07,90.93 76.45,91.31 76.45,93.34 76.19,93.6 75.56,93.6 75.52,93.55 75.52,92.45 75.15,92.08 74.36,92.08 74.25,91.96 72.31,91.96 72.03,91.68 72.03,91.22 72.08,91.17 72.35,91.17
V3P3 on TOP: 73.97,96.74 73.97,97.77 73.63,98.11 71.75,98.11 71.6,97.96 71.6,96.9 71.85,96.64 73.87,96.64
V3P3 on TOP: 58.45,7.75 56.72,7.66 56.72,5.71 56.85,5.59 57.05,5.59 57.18,5.46 57.18,4.83 57.2,4.81 57.2,4.66 57.08,4.54 53.68,4.54 53.57,4.64 53.57,5.2 53.26,5.51 50.9,5.51 48.28,8.13 48.28,10.47 43.65,15.1 31.74,15.1 27.1,19.74 27.1,23.53 30.38,26.81 46.23,26.81 50.41,30.99 61.72,30.99 65.96,26.75 65.96,14.87 63.41,12.32 59.7,12.32 59.38,11.99 59.38,10.92 59.37,10.91 58.52,10.91 58.49,10.87 58.49,7.78
V3P3 on BOTTOM: 72.08,92.16 71.79,91.87 71.79,90.99 72.29,90.48 75.72,90.48 75.83,90.59 75.83,91.98 75.65,92.16
V3P3 on BOTTOM: 58.04,7.84 58.04,10.75 52.23,10.75 50.11,8.64 50.11,5.84 50.62,5.33 53.98,5.33 55.18,4.13 55.18,3.37 55.5,3.05 57.38,3.05 58.04,3.7 58.04,5.56 57.52,6.07 57.52,7.33
V3P3 on BOTTOM: 74.51,96.99 74.5,96.99 74.5,97.62 74.23,97.89 72.39,97.89 72.1,98.19 71.77,98.19 71.52,97.94 71.52,96.85 71.85,96.52 74.04,96.52
V3P3 on PWR1#4: 46.74,0.64 46.74,25.4 62.36,25.4 62.36,14.25 63.78,12.83 70.97,12.83 78.49,20.34 78.49,63.35 75.31,66.53 75.31,82.66 65.41,92.56 65.41,101.62 69.45,105.66 95.88,105.66 95.88,0.64
V5P0 on TOP: 67.94,16.26 67.94,7.37 69.98,5.33 69.98,2.67 72.01,2.67 72.14,2.79 72.14,6.45 74.68,8.99 77.45,8.99 78.87,10.41 78.87,13.84 78.03,14.68 74.09,14.68 72.26,16.51 68.2,16.51
V5P0 on TOP: 23.88,100.71 22.69,100.71 22.57,100.83 21.45,100.83 21.43,100.85 21.43,101.8 21.68,102.05 23.67,102.05 23.88,101.84
V5P0 on TOP: 28.09,6.83 28.09,5 28.96,4.14 28.96,2.36 30.62,2.36 30.63,2.37 30.76,2.37 30.91,2.52 30.91,2.61 30.93,2.62 30.93,6.75 30.72,6.96 28.22,6.96
V5P0 on TOP: 38.35,39.08 38.28,39 38.28,37.17 38.63,36.82 38.63,34.62 38.92,34.33 40.26,34.33 41.02,35.09 41.02,39.08
V5P0 on TOP: 38.91,6.68 38.91,4.85 39.78,3.99 39.78,2.21 41.91,2.21 42.47,2.77 42.47,6.65 42.32,6.81 39.04,6.81
V5P0 on TOP: 58.45,5.69 57.66,5.69 57.48,5.51 57.48,3.3 58.04,2.74 58.04,1.15 58.21,0.98 66.06,0.98 66.27,1.18 66.27,3.86 65.99,4.13 63.62,4.13 62.75,3.27 60.14,3.27 59.94,3.46 59.94,4.16 60.4,4.62 60.4,5.33 59.99,5.74 59.21,5.74 59.16,5.69 59.16,4.72 59.15,4.72 59.15,4.46 58.97,4.27 58.54,4.27 58.37,4.45 58.37,4.76 58.45,4.83
V5P0 on BOTTOM: 67.64,17.8 67.64,10.7 69.89,8.45 73.86,8.45 75.2,9.79 78.51,9.79 79.71,10.99 79.71,18.29 79.18,18.81 73.91,18.81 73.21,18.12 67.96,18.12
V5P0 on SIG1#3: 26.86,42.86 29.21,40.51 29.21,38.86 28.32,37.97 10.67,37.97 3.68,30.99 3.68,12.95 15.75,0.89 77.47,0.89 94.87,18.29 94.87,111 85.85,120.02 17.27,120.02 10.41,113.16 10.41,102.36 12.45,100.33 22.1,100.33 22.99,101.22 22.99,102.11 22.97,102.13 22.97,107.37 22.91,107.43 23.81,108.33 42.67,108.33 45.21,110.87 45.21,115.57 46.1,116.46 63.5,116.46 65.21,114.74 65.21,111.19 68.58,107.82 75.56,107.82 80.52,102.87 80.52,51.56 66.93,37.97 47.62,37.97 32.64,22.99 16.13,22.99 15.11,24 15.11,25.65 15.88,26.42 32.51,26.42 48.64,42.55 48.64,45.97 47.24,47.37 27.81,47.37 26.86,46.42
V5P0_HDR on TOP: 6.31,47.78 6.31,48.46 6.51,48.66 7.49,48.66 7.66,48.49 9.95,48.49 9.98,48.46 9.98,47.72 9.95,47.7 7.56,47.7 7.4,47.53 6.56,47.53
V5P0_HDR on SIG2#6: 27.49,49.2 5.78,49.2 5.14,48.57 5.14,40.95 9.97,36.12 28.38,36.12 30.29,38.03 30.29,46.41
VBAT on TOP: 30.87,33.62 31.28,34.03 34,34.03 34.39,33.64 34.39,32.25 34.27,32.14 31.1,32.14 30.87,32.37
VBAT on BOTTOM: 49.66,37.34 50.55,38.23 50.55,43.56 50.42,43.69 46.29,43.69 45.69,43.09 45.69,35.04 44.95,34.3 35.41,34.3 34.99,34.72 34.99,42.61 35.05,42.67 35.05,43.31 34.42,43.94 30.86,43.94 30.23,43.31 30.23,27.6 31.8,26.03 44.32,26.03 49.66,31.37
VBUS_HEADER on TOP: 75,15.69 75.6,15.09 75.64,15.09 75.76,14.98 78.39,14.98 78.64,15.22 78.64,24.3 78.38,24.56 75,24.56
VBUS_HEADER on PWR2#5: 76.46,14.5 75.67,15.3 75.67,24.8 76.34,25.48 81.26,25.48 82.01,24.74 82.01,15.46 81.05,14.5
VBUS_IN on TOP: 78.94,20.12 78.94,24.62 74.1,29.46 74.1,29.47 74.06,29.51 72.39,29.51 72.34,29.57 72.34,32.89 73.08,33.63 76.44,33.63 78.01,32.06 80.29,32.06 81.58,30.76 81.58,20.18 81.33,19.93 79.13,19.93
VBUS_IN on TOP: 87.51,36.71 86.36,37.86 86.36,51.56 87.62,52.82 90.41,52.82 90.81,52.43 90.81,50.45 89.21,48.86 89.21,39.5 91.19,37.53 93.66,37.53 94.1,37.08 94.1,35.88 94.09,35.87 94.09,33.79 93.88,33.59 91.39,33.59 90.74,34.24 88.03,34.24 87.54,34.73 86.17,34.73 86.15,34.75 86.15,35.08 86.16,35.09 87.48,35.09 87.51,35.12
VBUS_IN on BOTTOM: 93.81,34.16 87.35,34.16 83.96,37.55 80.72,37.55 79.31,36.14 79.31,27.76 81.79,25.28 81.79,20.88 80.9,19.98 76.96,19.98 75.83,21.12 75.83,24.7 71.84,28.68 71.84,40.11 73.27,41.53 87.32,41.53 91.78,37.07 93.19,37.07 93.81,36.46
VDD on BOTTOM: 69.45,58.66 69.45,59.18 69.42,59.2 68.29,59.2 68.11,59.38 67.88,59.38 67.83,59.33 67.83,58.9 68.07,58.66
VDD on BOTTOM: 57.31,56.71 56.94,57.07 56.94,67.12 56.95,67.13 56.95,68.48 57.31,68.84 57.32,68.84 57.48,69 59.43,69 59.45,69.01 61.1,69.01 62.4,67.71 62.52,67.71 62.53,67.71 63.01,67.71 63.14,67.59 63.14,66.9 62.85,66.61 59.88,66.61 59.81,66.55 59.81,63.85 59.87,63.79 59.88,63.79 60.65,63.79 60.68,63.76 60.68,63 60.51,62.83 59.76,62.83 59.6,62.68 59.6,61.98 59.78,61.81 60.14,61.81 60.22,61.88 60.66,61.88 60.66,61.24 60.46,61.04 59.62,61.04 59.32,61.33 58.58,61.33 58.51,61.26 58.51,58.66 58.93,58.24 61.35,58.24 61.5,58.39 62.07,58.39 62.14,58.31 62.14,57.25 62.13,57.24 62.05,57.24 62.05,57.24 61.39,57.24 61.36,57.21 60.7,57.21 60.2,56.71
VDD on PWR1#4: 64.24,56.9 63.63,57.51 63.63,57.79 63.77,58.05 63.63,58.32 63.63,58.69 63.76,58.95 63.63,59.21 63.63,59.49 63.76,59.82 63.5,60.06 63.49,60.06 63.41,60.14 63.4,60.2 63.44,60.23 63.67,60.77 63.13,60.55 63.13,60.53 63.08,60.47 62.96,60.59 62.96,60.61 62.7,60.86 62.37,60.71 62.12,60.71 61.84,60.87 61.57,60.71 61.32,60.71 61.04,60.87 60.77,60.71 59.92,60.71 57.79,62.84 57.79,69.47 64.28,69.47 66.43,67.32 66.46,67.25 66.43,67.18 66.42,66.72 66.87,66.73 66.95,66.76 67.02,66.73 67.23,66.52 67.26,66.45 67.23,66.38 67.22,65.92 67.67,65.93 67.75,65.96 67.82,65.93 68.03,65.72 68.06,65.65 68.03,65.58 68.02,65.12 68.47,65.13 68.55,65.16 68.62,65.13 69.34,64.41 69.34,61.58 69.3,61.57 69.04,61.32 69.19,60.99 69.23,60.94 69.23,60.87 69.22,60.66 69.34,60.5 69.34,57.64 68.6,56.9 68.54,56.9 68.53,56.91 68.28,57 68.04,56.9
CVDDQ on TOP: 77.85,82.68 81.03,82.68 81.66,83.31 81.66,85.72 81.15,86.23 70.23,86.23 69.22,85.22 69.22,74.93 69.34,74.8 70.1,74.8 70.23,74.93 70.23,76.2 70.36,76.33 70.99,76.33 71.37,75.95 71.37,74.93 71.5,74.8 72.14,74.8 72.14,76.2 72.39,76.45 73.41,76.45 73.66,76.2 73.66,74.93 73.79,74.8 74.42,74.8 74.55,74.93 74.55,79.38
CVDDQ on BOTTOM: 73.28,62.6 69.69,62.6 69.68,62.61 68.1,62.61 68.01,62.7 68.01,63.13 68.2,63.31 74.77,63.31 74.78,63.32 75.83,63.32 79.11,66.59 79.11,80.3 76.68,82.72 76.68,87.63 80.24,91.19 80.24,98.2 78.49,99.95 69.95,99.95 63.96,93.96 7.26,93.96 6.35,94.87 6.35,106.55 8,108.2 38.58,108.2 43.65,113.27 63.92,113.27 66.17,115.53 84.37,115.53 94.23,105.66 94.23,83.23 90.68,79.67 90.68,57.78 89.71,56.82 89.71,56.77 87.94,55 87.94,51 86.6,49.66 75.56,49.66 74.04,51.18 74.04,54.1 74.93,54.99 77.34,54.99 78.74,53.59 80.26,53.59 80.77,54.1 80.77,57.28 79.69,58.36 77.52,58.36
REG_VBATT on TOP: 34.26,31.61 32.62,31.61 32.41,31.4 32.41,29.91 32.45,29.87 32.45,28.55 33.89,27.11 43.6,27.11 43.89,27.4 43.89,28.9 43.55,29.24 40.44,29.24 40.37,29.17 35.04,29.17 34.34,29.87 34.34,31.53
REG_VBATT on PWR1#4: 36.3,25.91 31.62,30.59 31.62,35.84 33.76,37.97 66.04,37.97 66.04,29.44 62.51,25.91
U3RX_VDDQ on BOTTOM: 73.82,65.25 73.82,65.25 74.03,65.25 74.19,65.41 74.19,67.99 73.85,68.33 72.33,68.33 72.32,68.32 72.32,66.54 71.69,65.91 69.63,65.91 69.34,65.62 69.34,65.31 69.4,65.25
U3TX_VDDQ on BOTTOM: 69.97,68.96 69.97,67.87 70.25,67.58 70.25,67.58 70.46,67.36 71.96,67.36 72.05,67.45 72.05,68.75 71.84,68.96
U3TX_VDDQ on PWR2#5: 66.55,60.83 66.55,63.01 67.16,63.63 70.08,63.63 71.37,64.92 71.37,68.96 76.07,68.96 76.07,63.48 73.43,60.83
VIO1 on TOP: 19.95,100.83 18.25,100.83 18.13,100.71 17.44,100.71 17.41,100.74 17.41,103.24 17.53,103.36 19.81,103.36 19.84,103.33 19.84,101.6 19.97,101.47 19.96,101.47 19.96,100.84
VIO1 on TOP: 25.19,106.09 21.66,106.09 21.49,105.92 21.49,105.33 21.69,105.13 25.07,105.13 25.28,105.33 25.28,106.03 25.21,106.1
VIO1 on BOTTOM: 62.59,57.21 63.59,57.21 63.65,57.26 63.65,57.67 63.61,57.7 63.54,57.7 63.33,57.91 63.33,58.48 63.26,58.55 62.51,58.55 62.33,58.37 62.33,57.46
VIO1 on PWR1#4: 0.64,0.64 0.64,120.01 39.12,120.01 39.12,118.14 39.08,118.13 38.25,117.09 39.08,116.05 39.12,116.05 39.12,110.52 39.08,110.51 38.25,109.47 39.08,108.43 39.12,108.43 39.12,95.02 41.64,92.49 41.64,92.46 41.64,91.94 42.12,91.29 42.93,91.17 42.96,91.17 57.28,76.86 57.28,73.01 57.22,72.92 57.11,72.94 56.66,72.97 56.54,72.54 56.54,72.45 56.47,72.4 56.19,72.03 56.51,71.7 56.73,71.75 56.88,71.92 56.9,72.06 56.87,72.19 56.88,72.28 56.94,72.33 57.03,72.36 57.11,72.41 57.22,72.43 57.28,72.34 57.28,62.63 59.71,60.2 62.63,60.2 62.7,60.13 62.64,60.07 62.62,60.07 62.42,59.52 62.96,59.73 62.96,59.75 63.02,59.81 63.12,59.71 63.12,57.3 64.03,56.39 66.04,56.39 66.04,52.82 66.01,52.79 65.98,52.76 65.9,52.73 65.83,52.76 65.44,52.84 65.22,52.52 65.45,52.18 65.85,52.28 65.92,52.31 65.99,52.28 66.04,52.24 66.04,38.48 33.55,38.48 31.11,36.05 31.11,33.4 30.88,33.03 31.11,32.66 31.11,30.37 36.09,25.4 46.23,25.4 46.23,0.64
VIO1_HDR on TOP: 17.03,94.33 17.76,93.59 17.76,81.67 16.76,80.67 13.27,80.67 13,80.94 13,83.23 12.48,83.74 10.45,83.74 10.25,83.54 10.25,80.92 10.01,80.68 7.11,80.68 5.78,79.35 5.78,47.9 6.34,47.34 7.5,47.34 7.65,47.48 10.06,47.48 10.11,47.43 10.11,45.04 10.83,44.32 12.82,44.32 13.15,44.65 13.15,47.26 13.37,47.48 15.85,47.48 15.9,47.42 15.9,39.69 15.28,39.06 2.91,39.06 1.27,40.71 1.27,93.02 2.58,94.33
VIO2 on TOP: 64.41,66.79 64.84,66.79 64.99,66.93 64.99,68.4 64.75,68.64 64.24,68.64 64.08,68.49 64.08,67.12
VIO2 on BOTTOM: 64.28,67.18 65.34,67.18 65.34,68.45 65.24,68.55 64.25,68.55 64.13,68.44 64.13,67.21 64.16,67.18
VIO2 on PWR2#5: 26.16,14.48 26.16,74.06 36.94,84.84 65.28,84.84 65.28,67.67 64.41,66.8 59.97,66.8 39.24,46.08 39.24,14.48
VIO3 on PWR2#5: 39.75,14.48 39.75,45.87 60.18,66.29 64.62,66.29 65.79,67.46 65.79,113.56 67.29,115.06 78.29,115.06 79.21,114.14 79.21,69.47 70.87,69.47 70.87,65.13 69.87,64.14 66.95,64.14 66.04,63.22 66.04,52.05 51.44,37.44 51.44,27.45 55.24,23.64 55.24,14.48
VIO4 on BOTTOM: 68.08,66.73 68.26,66.55 68.64,66.55 68.89,66.79 68.89,67.07 69.1,67.28 69.76,67.28 69.79,67.31 69.79,67.69 69.69,67.79 68.75,67.79 68.64,67.69 68.12,67.69 68.08,67.65
VIO4 on PWR1#4: 63.99,13.34 62.87,14.46 62.87,25.55 66.55,29.23 66.55,56.39 68.81,56.39 69.85,57.43 69.85,64.62 64.49,69.98 57.78,69.98 57.78,77.07 39.62,95.23 39.62,120.01 95.88,120.01 95.88,106.17 69.24,106.17 64.9,101.83 64.9,92.35 74.8,82.44 74.8,66.32 77.98,63.14 77.98,20.55 70.76,13.34
VIO5 on BOTTOM: 66.61,58.29 66.61,57.28 66.74,57.15 68.14,57.15 68.14,58.29 68.01,58.42 66.74,58.42
VIO5 on BOTTOM: 26.77,118.97 26.77,117.15 27.25,116.67 31.2,116.67 31.71,116.16 33.27,116.16 33.84,116.74 33.84,118.54 32.94,119.45 27.24,119.45
VIO5 on PWR2#5: 0.64,0.64 0.64,120.01 95.88,120.01 95.88,0.64 ; 3 cut-outs
N13394127 on TOP: 35.31,33.02 35.31,30.61 35.56,30.35 35.58,30.35 36.46,29.47 43.49,29.47 43.56,29.54 43.56,32.38 42.55,33.4 35.69,33.4
N13394127 on SIG2#6: 65.9,56.51 66.47,55.94 67.53,55.94 67.89,56.3 67.89,58.14 67.53,58.5 67.51,58.49 66.45,58.49 66.45,58.96 65.98,59.43 65.65,59.43 65.54,59.31 65.54,58.25 65.9,57.89
N17004628 on TOP: 85.22,34.87 85.22,29.72 84.96,29.46 83.31,29.46 83.24,29.54 83.24,33.66 83.16,33.73 81.08,33.73 80.39,34.42 79.5,34.42 79.38,34.54 79.38,35.94 79.79,36.35 81.26,36.35 81.54,36.07 81.54,35.17 81.63,35.09 81.68,35.09 81.68,35.08 81.89,35.08 81.89,35.08 83.06,35.08 83.06,35.08 83.2,35.08 83.2,35.09 85.01,35.09
N17006752 on TOP: 79.46,34.04 78.24,35.26 76.66,35.26 76.57,35.17 76.57,33.92 76.61,33.88 77.66,33.88 78.78,32.77 80.64,32.77 80.44,34.04
N17006789 on TOP: 78.31,41.31 76.67,41.31 76.27,40.91 76.27,35.94 76.59,35.63 78.32,35.63 78.51,35.82 78.51,41.1
N17020961 on TOP: 93.74,33.17 91.57,33.17 90.69,32.29 90.69,26.04 90.76,25.97 93.7,25.97 94.35,26.62 94.35,32.55
N17020961 on BOTTOM: 94.51,33.32 90.68,33.32 90.68,25.95 94.51,25.95
N17073855 on TOP: 94.14,66.03 94.14,54.36 93.63,53.85 92.08,53.85 91.82,53.59 91.82,51.46 93.73,49.56 93.73,45.67 94.11,45.29 95.89,45.29 95.94,45.34 95.94,67.44 95.89,67.44 95.89,67.97 95.28,68.58 92.08,68.58 91.82,68.33 91.82,66.14 91.93,66.03
N17073855 on BOTTOM: 93.83,45.57 94.11,45.29 95.87,45.29 95.87,67.98 95.47,68.38 92.31,68.38 91.92,67.99 91.92,66.62 92.32,66.22 93.19,66.22 93.44,65.98 93.43,65.97 93.43,54.04 91.92,52.54 91.92,50.55 93.84,48.63 93.84,45.58
N20153874 on TOP: 91.7,56.04 91.16,55.5 88.77,55.5 88.39,55.12 88.39,53.61 88.75,53.26 90.59,53.26 91.82,54.48 93.1,54.48 93.1,56 93.06,56.04
N20153874 on BOTTOM: 92,53.3 93.1,54.4 93.1,56.13 89.57,56.13 88.54,55.1 88.54,53.55 88.78,53.3

Small or netless copper shapes (teardrops, artwork), in the pictures only: 1 on TOP, 1 on BOTTOM

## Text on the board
BOTTOM: 8 | BOTTOM
Board Geometry/Soldermask Bottom: SOLDERMASK BOTTOM
Ref Des/Silkscreen Bottom: A | K | N | VBAT
TOP: 1 | TOP
Ref Des/Assembly Top: TRST | TMS | TDI | V1P8 | TCK | V2P5 | V3P3 | 5V DC | INPUT | CON | RESET | SWITCH | VIO1 | A | GND | SW | CTRL | CTRL4 | LT | JTAG CONN | 3.DIP | 2.PMODE | 1.CON | EEPROM | FX3 | PPORT | CYUSB3KIT-001 FX3 DVK | address switch | VIO2 | 3 | 2 | 1 | I2C_SDA_FX3 | I2C_SCL_FX3 | V1P2 | 1.UART | SPI HEADER | 3.SPI | VIO3 | VIO5 | V5P0 | VBATT | REG | CLOCK IN | VIO4 | CHARGE | DETECT | CVDDQ | 19.2 MHz XTAL | PMODE0 | PMODE1 | PMODE2 | I2C_SDA | PMODE | GPIO45 | I2C_SCL | SPI FLASH | I2S HEADER | OTG_ID | CLOCK | IN_32 | VBUS | USB_DRV | VBUS_IN | USB | Connector | FAULTA_L
Board Geometry/Soldermask Top: SOLDERMASK TOP
Ref Des/Silkscreen Top: 1 | 2 | 3
GND1#2: GND1#2
SIG1#3: SIG1#3
PWR1#4: PWR1#4
PWR2#5: PWR2#5
SIG2#6: SIG2#6
GND2#7: GND2#7
User.7: PCB:600-60015-01 | PCB:600-60015-01 REV03
User.8: PCB:600-60015-01 REV03
User.9: PCB:600-60015-01 REV03
User.10: FAB: 610-60012-01 REV03 | DRAWN: | CHECKED: | QUALITY CONTROL: | RELEASED: | 305-PD-11-0618 | DATED: | SEP 2011 | TITLE: | SCALE: | COMPANY: | 408 747 1237 (phone) | 1149 Tasman Drive, | CODE: | SIZE: | Sunnyvale Ca 94089 | FX3_DVKDEVICE_Brd_Rev3 | 408 747 1239 (fax) | PAC NO: 305-PD-11-0618 | DRAWING NO: | SHEET:     OF | REV:3 | LAYERS | L8 | L4 | L6 | L5 | L7 | L3 | L2 | L1 | BOTTOM | PWR2 | GND1 | SIG1 | GND2 | PWR1 | SIG2 | TOP | TYPE | BOTTOM SIDE SOLDER MASK | TOP SIDE SOLDER MASK | COPPER | COPPER+PLATING | PCB STACK UP | PREPREG | CORE | FAB | TOTAL | +PLATING | THICKNESS(MILS) | 10.50 | 63.00 MILS | 0.50 | 7.50 | 0.70 | 5.00 | 0.90 | 10.0 | 0.7 | 0.50MILS | 1.60MM | MILS | 19MILS,50 OHM+/-10% | 5MILS,50 OHM +/-10% | SINGLE ENDED | BOARD THICKNESS : 0.062" +/-0.006",MATERIAL 370HR | IMPEDANCE | 49.18 OHM | 49.28 OHM | OHM | 12/8/12 MILS, | DIFFERENTIAL | 100 OHM +/-10% | 97.1 OHM | BOARD DIMENSIONS ARE IN MILS[MM] | 14) NO VENDOR LOGO OR NAME ON THE BOARD. | 15) REMOVE ALL UNUSED PADS IN ALL INNER LAYERS | 13) PLATING: SOFT IMMERSION GOLD FINISH. | 10) DEBURR ALL SHARP EDGES | 11) BOW AND TWIST: SHOULD NOT EXCEED 0.005" PER INCH. | 12) PLATED PADS ON TOP AND BOTTOM MUST BE SAME HEIGHT | 1) FABRICATE BOARD PER IPC-A-600G | 2) MATERIAL 370HR 8 LAYER BOARD. | 3) BOARD THICKNESS : 0.062" +/-0.006". | 4) MINIMUM PLATING IN ALL THE THROUGH HOLE SHALL BE 0.001 INCH Cu. | 5) ALL HOLES ARE PLATED THROUGH UNLESS OTHERWISE SPECIFIED. | 6) HOLE SIZE ARE FINISHED SIZE. | 7) SOLDER MASK BOTH SIDE WITH BLUE LIQUID PHOTO IMAGABLE. | 8) FOR LAYER BUILD UP SEE STACK UP DETAIL. | 9) SILKSCREEN BOTH SIDE "WHITE EPOXY" OVER SOLDER MASK | NOTES : | AS CONDUCTOR PAD AND TRACE | LAYER DETAIL
User.11: DATE:SEP 2011 | NAME :  FX3_DVK_DEVICE_Brd_Rev3 | LAYER : | JOB: 305-PD-11-0618 | Rev.3
User.17: FIGURE | SIZE | 8.0 | 10.0 | 11.81 | 12.0 | 32.0 | 39.37 | 40.0 | 44.0 | 45.0 | 73.0 | 120.0 | 94.0 | 125.0 | 125.0x35.0 | 145.0x45.0 | DRILL CHART: TOP to BOTTOM | ALL UNITS ARE IN MILS | TOLERANCE | +3.0/-3.0 | +2.0/-0.0 | +2.0/-2.0 | PLATED | NON-PLATED | QTY | 415 | 236 | 5 | 47 | 10 | 4 | 157 | 9 | 7 | 3 | 2 | 1
User.19: BOARD OUTLINE
User.21: PASTEMASK BOTTOM
User.22: PASTEMASK TOP
User.23: ASSY:620-60013-01 REV03 | ASSEMBLY BOTTOM
User.24: ASSY:620-60013-01 | ASSY:620-60013-01 REV03 | ASSEMBLY TOP
User.25: SILKSCREEN TOP
User.26: SILKSCREEN BOTTOM
User.32: 2
User.33: 3
User.34: 7
User.35: 6
User.36: 4
User.37: 5
